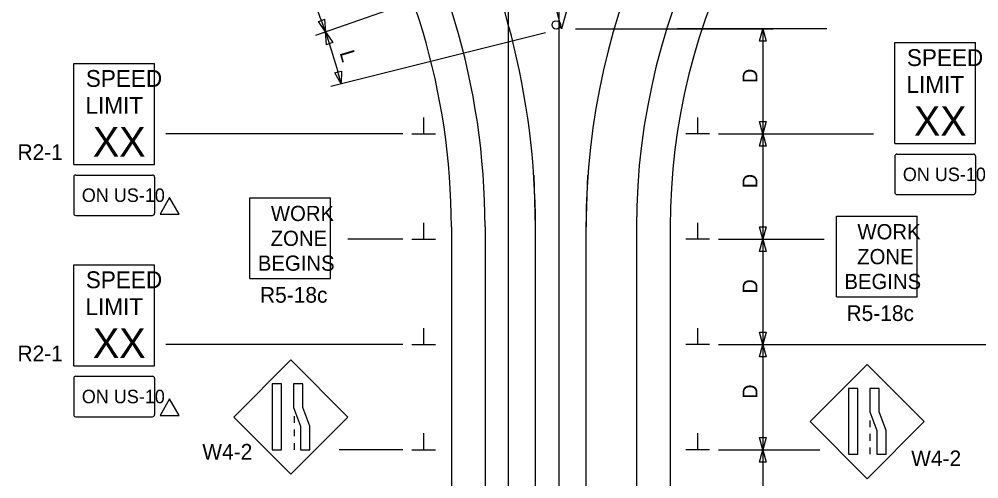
# Model space of a CAD drawing. Extents: x 16574 to 18479, y 5718 to 6974.
# Drawn here: x 16748.2 to 17204.3, y 6405.5 to 6623.9 of the extents above; entities that cross this region are included whole.
import ezdxf

# ---------------------------------------------------------------- set-up
doc = ezdxf.new("R2010")
doc.units = 0
for name, color, linetype in [('ALI_LEGAL_EX', 7, 'Continuous'), ('PAVT_EDGE_EX', 7, 'Continuous'), ('TRAFFIC_SIGNS_PR', 7, 'Continuous'), ('TYPICAL_TEXT_DIMEN_PR', 7, 'Continuous')]:
    doc.layers.add(name, color=color, linetype=linetype)

msp = doc.modelspace()

# ---------------------------------------------------------------- linework, layer by layer
at = {"layer": 'ALI_LEGAL_EX'}
for p, q in [((16980.68, 6974.12), (16980.68, 6155.98)), ((17004.68, 6974.12), (17004.68, 6155.98)), ((16980.68, 6877.04), (16980.68, 6013.12)), ((17004.68, 6877.04), (17004.68, 6013.12)), ((16993.65, 6024.8), (16993.65, 6525.15)), ((17017.65, 6024.8), (17017.65, 6525.15))]:
    msp.add_line(p, q, dxfattribs=at)
for points in [[(16993.6, 6524.8), (16993.65, 6525.15), (16993.08, 6549.79)], [(17017.7, 6524.8), (17017.65, 6525.15), (17018.48, 6549.78)], [(16993.65, 6424.8), (16993.65, 6449.8)], [(17017.65, 6424.8), (17017.65, 6449.8)]]:
    msp.add_lwpolyline(points, dxfattribs=at)
for centre, radius, start, end in [((16629.65, 6525.15), 364, 0, 57.2958), ((17357.65, 6525.15), 340, 129.5666, 180)]:
    msp.add_arc(centre, radius, start, end, dxfattribs=at)
at = {"layer": 'PAVT_EDGE_EX'}
for p, q in [((16953.65, 6525.15), (16953.65, 6186.91)), ((16969.65, 6525.15), (16969.65, 6186.91)), ((17041.65, 6525.15), (17041.65, 6186.91)), ((17057.65, 6525.15), (17057.65, 6186.91))]:
    msp.add_line(p, q, dxfattribs=at)
for centre, radius, start, end in [((16629.65, 6525.15), 388, 14.0482, 66.0906), ((16629.65, 6525.15), 340, 0, 66.0906), ((17357.65, 6525.15), 364, 124.3812, 165.0045), ((16629.65, 6525.15), 324, 0, 66.0906), ((17357.65, 6525.15), 316, 124.3812, 180), ((17357.65, 6525.15), 300, 124.3812, 180), ((17357.65, 6525.15), 300, 180, 180.00000277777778)]:
    msp.add_arc(centre, radius, start, end, dxfattribs=at)
at = {"layer": 'TRAFFIC_SIGNS_PR'}
for p, q in [((17164.39, 6612.74), (17202.79, 6612.74)), ((17164.39, 6564.74), (17164.39, 6612.74)), ((17202.79, 6564.74), (17202.79, 6612.74)), ((16774.16, 6602.83), (16812.56, 6602.83)), ((16774.16, 6554.83), (16774.16, 6602.83)), ((16812.56, 6554.83), (16812.56, 6602.83)), ((17164.39, 6564.74), (17202.79, 6564.74)), ((17164.39, 6558.74), (17164.39, 6541.54)), ((17165.39, 6559.74), (17201.79, 6559.74)), ((17202.79, 6558.74), (17202.79, 6541.54)), ((16774.16, 6554.83), (16812.56, 6554.83)), ((16775.16, 6549.83), (16811.56, 6549.83)), ((16774.16, 6548.83), (16774.16, 6531.63)), ((16812.56, 6548.83), (16812.56, 6531.63)), ((17165.39, 6540.54), (17201.79, 6540.54)), ((16857.88, 6500.59), (16857.88, 6538.99)), ((16857.88, 6538.99), (16896.28, 6538.99)), ((16896.28, 6500.59), (16896.28, 6538.99)), ((16775.16, 6530.63), (16811.56, 6530.63)), ((17136.64, 6491.91), (17136.64, 6530.31)), ((17136.64, 6530.31), (17175.04, 6530.31)), ((17175.04, 6491.91), (17175.04, 6530.31)), ((16774.16, 6507.19), (16812.56, 6507.19)), ((16774.16, 6459.19), (16774.16, 6507.19)), ((16812.56, 6459.19), (16812.56, 6507.19)), ((16857.88, 6500.59), (16896.28, 6500.59)), ((17136.64, 6491.91), (17175.04, 6491.91)), ((16774.16, 6459.19), (16812.56, 6459.19)), ((16877.34, 6461.96), (16850.19, 6434.81)), ((16904.5, 6434.81), (16877.34, 6461.96)), ((17151.29, 6459.85), (17124.14, 6432.69)), ((17178.45, 6432.69), (17151.29, 6459.85)), ((16775.16, 6454.19), (16811.56, 6454.19)), ((16774.16, 6453.19), (16774.16, 6435.99)), ((16812.56, 6453.19), (16812.56, 6435.99)), ((16775.16, 6434.99), (16811.56, 6434.99)), ((16850.19, 6434.81), (16877.35, 6407.65)), ((16877.34, 6407.66), (16904.5, 6434.81)), ((16878.98, 6435.3), (16878.98, 6432.1)), ((17124.14, 6432.69), (17151.29, 6405.54)), ((17151.29, 6405.54), (17178.45, 6432.69)), ((17152.53, 6433.19), (17152.53, 6429.99)), ((16878.98, 6428.9), (16878.98, 6425.7)), ((17152.53, 6426.79), (17152.53, 6423.59)), ((16878.98, 6422.5), (16878.98, 6419.3)), ((17152.53, 6420.39), (17152.53, 6417.19))]:
    msp.add_line(p, q, dxfattribs=at)
for points in [[(16868.45, 6450.55), (16868.45, 6419.3), (16872.94, 6419.3), (16872.94, 6450.55)], [(16878.58, 6450.55), (16878.58, 6439.37), (16881.93, 6430.48), (16881.93, 6419.3), (16886.42, 6419.3), (16886.42, 6430.48), (16883.08, 6439.37), (16883.08, 6450.55)], [(17142.4, 6448.43), (17142.4, 6417.19), (17146.89, 6417.19), (17146.89, 6448.43)], [(17152.53, 6448.43), (17152.53, 6437.25), (17155.88, 6428.37), (17155.88, 6417.19), (17160.37, 6417.19), (17160.37, 6428.37), (17157.03, 6437.25), (17157.03, 6448.43)]]:
    msp.add_lwpolyline(points, close=True, dxfattribs=at)
msp.add_circle((17003.5, 6621.15), 2, dxfattribs=at)
for centre, start, end in [((17165.39, 6558.74), 90, 180), ((17201.79, 6558.74), 0, 90), ((16775.16, 6548.83), 90, 180), ((16811.56, 6548.83), 0, 90), ((17165.39, 6541.54), 180, 270), ((17201.79, 6541.54), 270, 0), ((16775.16, 6531.63), 180, 270), ((16811.56, 6531.63), 270, 0), ((16775.16, 6453.19), 90, 180), ((16811.56, 6453.19), 0, 90), ((16775.16, 6435.99), 180, 270), ((16811.56, 6435.99), 270, 0)]:
    msp.add_arc(centre, 1, start, end, dxfattribs=at)
at = {"layer": 'TYPICAL_TEXT_DIMEN_PR'}
for p, q in [((16968.07, 6643.79), (16889.16, 6616.13)), ((16890.46, 6622.79), (16891.94, 6623.31)), ((16893.88, 6617.78), (16890.46, 6622.79)), ((16891.94, 6623.31), (16893.42, 6623.83)), ((16893.42, 6623.83), (16893.88, 6617.78)), ((17012.72, 6619.33), (17106.65, 6619.33)), ((17132.09, 6619.33), (17060.95, 6619.33)), ((17100.08, 6613.47), (17101.65, 6619.33)), ((17101.65, 6619.33), (17103.22, 6613.47)), ((17101.65, 6619.33), (17101.65, 6569.33)), ((16894.34, 6611.73), (16893.88, 6617.78)), ((16893.88, 6617.78), (16897.3, 6612.77)), ((16998.34, 6617.4), (16896.42, 6591.9)), ((17101.65, 6613.47), (17100.08, 6613.47)), ((17103.22, 6613.47), (17101.65, 6613.47)), ((16895.82, 6612.25), (16894.34, 6611.73)), ((16897.3, 6612.77), (16895.82, 6612.25)), ((16898.33, 6598.42), (16899.85, 6598.8)), ((16901.28, 6593.11), (16898.33, 6598.42)), ((16899.85, 6598.8), (16901.38, 6599.18)), ((16901.38, 6599.18), (16901.28, 6593.11)), ((16940.52, 6569.33), (16940.52, 6577.11)), ((17070.77, 6569.33), (17070.77, 6577.11)), ((17101.65, 6569.33), (17100.08, 6575.19)), ((17100.08, 6575.19), (17101.65, 6575.19)), ((17101.65, 6575.19), (17103.22, 6575.19)), ((17103.22, 6575.19), (17101.65, 6569.33)), ((16930.65, 6569.33), (16817.92, 6569.33)), ((16934.9, 6569.33), (16946.15, 6569.33)), ((17076.4, 6569.33), (17065.15, 6569.33)), ((17080.65, 6569.33), (17154.23, 6569.33)), ((17100.08, 6563.47), (17101.65, 6569.33)), ((17101.65, 6569.33), (17101.65, 6519.33)), ((17101.65, 6569.33), (17103.22, 6563.47)), ((17101.65, 6563.47), (17100.08, 6563.47)), ((17103.22, 6563.47), (17101.65, 6563.47)), ((16940.52, 6519.33), (16940.52, 6527.11)), ((17070.77, 6519.33), (17070.77, 6527.11)), ((17101.65, 6519.33), (17100.08, 6525.19)), ((17100.08, 6525.19), (17101.65, 6525.19)), ((17101.65, 6525.19), (17103.22, 6525.19)), ((17103.22, 6525.19), (17101.65, 6519.33)), ((16930.65, 6519.33), (16904.43, 6519.33)), ((16934.9, 6519.33), (16946.15, 6519.33)), ((17076.4, 6519.33), (17065.15, 6519.33)), ((17080.65, 6519.33), (17130.84, 6519.33)), ((17100.08, 6513.47), (17101.65, 6519.33)), ((17101.65, 6519.33), (17101.65, 6469.33)), ((17101.65, 6519.33), (17103.22, 6513.47)), ((17101.65, 6513.47), (17100.08, 6513.47)), ((17103.22, 6513.47), (17101.65, 6513.47)), ((16940.52, 6469.33), (16940.52, 6477.11)), ((17070.77, 6469.33), (17070.77, 6477.11)), ((17101.65, 6469.33), (17100.08, 6475.19)), ((17100.08, 6475.19), (17101.65, 6475.19)), ((17101.65, 6475.19), (17103.22, 6475.19)), ((17103.22, 6475.19), (17101.65, 6469.33)), ((16930.65, 6469.33), (16817.92, 6469.33)), ((16934.9, 6469.33), (16946.15, 6469.33)), ((17076.4, 6469.33), (17065.15, 6469.33)), ((17080.65, 6469.33), (17237.03, 6469.33)), ((17100.08, 6463.47), (17101.65, 6469.33)), ((17101.65, 6469.33), (17101.65, 6419.33)), ((17101.65, 6469.33), (17103.22, 6463.47)), ((17101.65, 6463.47), (17100.08, 6463.47)), ((17103.22, 6463.47), (17101.65, 6463.47)), ((16940.52, 6419.33), (16940.52, 6427.11)), ((17070.77, 6419.33), (17070.77, 6427.11)), ((17101.65, 6419.33), (17100.08, 6425.19)), ((17100.08, 6425.19), (17101.65, 6425.19)), ((17101.65, 6425.19), (17103.22, 6425.19)), ((17103.22, 6425.19), (17101.65, 6419.33)), ((16930.65, 6419.33), (16900.37, 6419.33)), ((16934.9, 6419.33), (16946.15, 6419.33)), ((17076.4, 6419.33), (17065.15, 6419.33)), ((17080.65, 6419.33), (17128.86, 6419.33)), ((17100.08, 6413.47), (17101.65, 6419.33)), ((17101.65, 6419.33), (17101.65, 6369.33)), ((17101.65, 6419.33), (17103.22, 6413.47)), ((17101.65, 6413.47), (17100.08, 6413.47)), ((17103.22, 6413.47), (17101.65, 6413.47))]:
    msp.add_line(p, q, dxfattribs=at)
for points in [[(16819.76, 6539.08), (16815.24, 6531.24), (16824.29, 6531.24)], [(16819.76, 6443.44), (16815.24, 6435.61), (16824.29, 6435.61)]]:
    msp.add_lwpolyline(points, close=True, dxfattribs=at)
for start, end in [(19.32, 24.1124), (14.0482, 19.32)]:
    msp.add_arc((16629.65, 6525.15), 280, start, end, dxfattribs=at)

# ---------------------------------------------------------------- texts
at = {"layer": 'TRAFFIC_SIGNS_PR'}
for s, height, p in [('SPEED', 8, (17170.16, 6601.6)), ('SPEED', 8, (16779.93, 6591.7)), ('LIMIT', 8, (17170, 6588.8)), ('LIMIT', 8, (16779.77, 6578.9)), ('XX', 14.031, (17173.51, 6568.5)), ('XX', 14.031, (16783.28, 6558.59)), ('R2-1', 7.44, (16747.43, 6556.97)), ('ON US-10', 6.4, (17168.23, 6546.94)), ('ON US-10', 6.4, (16778, 6537.03)), ('WORK', 7.217, (16867.88, 6527.96)), ('ZONE', 7.217, (16867.77, 6516.15)), ('WORK', 7.217, (17146.65, 6519.27)), ('ZONE', 7.217, (17146.53, 6507.46)), ('BEGINS', 7.217, (16861.69, 6504.34)), ('SPEED', 8, (16779.93, 6496.06)), ('BEGINS', 7.217, (17140.46, 6495.65)), ('R5-18c', 7.44, (16862.7, 6489.15)), ('LIMIT', 8, (16779.77, 6483.26)), ('R5-18c', 7.44, (17141.46, 6480.47)), ('XX', 14.031, (16783.28, 6462.95)), ('R2-1', 7.44, (16747.43, 6461.33)), ('ON US-10', 6.4, (16778, 6441.39)), ('W4-2', 7.441, (16835.28, 6414.63)), ('W4-2', 7.441, (17172.19, 6411.5))]:
    msp.add_text(s, height=height, dxfattribs=at).set_placement(p)
at = {"layer": 'TYPICAL_TEXT_DIMEN_PR'}
for s, rotation, p in [('L', 286.685, (16900.47, 6607.93)), ('D', 90, (17099.09, 6593.55)), ('D', 90, (17099.09, 6543.55)), ('D', 90, (17099.09, 6493.55)), ('D', 90, (17099.09, 6443.55))]:
    msp.add_text(s, height=7, rotation=rotation, dxfattribs=at).set_placement(p)

doc.saveas('drawing.dxf')
